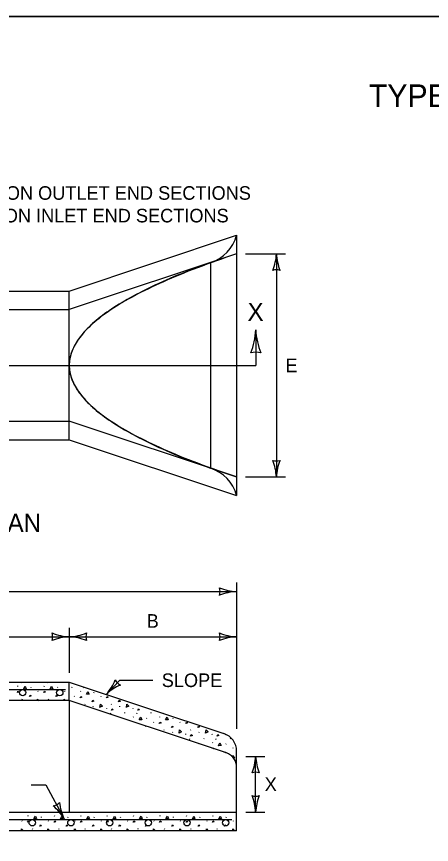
# Model space of a CAD drawing. Extents: x 49991.4 to 50021, y 49987.6 to 50011.4.
# Drawn here: x 50010.636 to 50012.469, y 49995.339 to 49998.999 of the extents above; entities that cross this region are included whole.
import ezdxf

# ---------------------------------------------------------------- set-up
doc = ezdxf.new("R2010")
doc.units = 0
for name, color, linetype in [('Level 1', 7, 'Continuous'), ('Level 2', 7, 'Continuous'), ('Level 3', 7, 'Continuous'), ('Level 4', 7, 'Continuous'), ('Level 6', 7, 'Continuous')]:
    doc.layers.add(name, color=color, linetype=linetype)

msp = doc.modelspace()

# ---------------------------------------------------------------- linework, layer by layer
at = {"layer": 'Level 1'}
for p, q in [((50010.8686, 49997.7858), (50011.6083, 49998.0325)), ((50011.6083, 49998.0325), (50011.6083, 49996.8818)), ((50011.4932, 49997.9121), (50011.4932, 49997.0023)), ((50009.6084, 49997.7858), (50010.8686, 49997.7858)), ((50010.8686, 49997.1282), (50010.8686, 49997.7858)), ((50009.6084, 49997.1282), (50010.8686, 49997.1282)), ((50010.8686, 49997.1282), (50011.6083, 49996.8818)), ((50009.6084, 49996.0573), (50010.8686, 49996.0573)), ((50010.6408, 49996.038), (50010.6418, 49996.0402)), ((50010.6552, 49996.0561), (50010.6562, 49996.0546)), ((50010.6562, 49996.0555), (50010.6572, 49996.0541)), ((50010.7195, 49996.0561), (50010.72, 49996.0573)), ((50010.7575, 49996.038), (50010.7585, 49996.0402)), ((50010.7719, 49996.0561), (50010.7729, 49996.0546)), ((50010.7729, 49996.0555), (50010.7738, 49996.0541)), ((50010.8362, 49996.0561), (50010.8367, 49996.0573)), ((50010.8686, 49996.0573), (50011.5522, 49995.8295)), ((50010.8686, 49995.975), (50010.8686, 49996.0573)), ((50010.8803, 49996.0334), (50010.8813, 49996.0356)), ((50010.6998, 49996.0324), (50010.7008, 49996.0346)), ((50010.7302, 49996.0169), (50010.7312, 49996.0154)), ((50010.8165, 49996.0324), (50010.8174, 49996.0346)), ((50010.8469, 49996.0169), (50010.8479, 49996.0154)), ((50010.9183, 49996.0153), (50010.9193, 49996.0175)), ((50010.9327, 49996.0334), (50010.9336, 49996.0319)), ((50010.9336, 49996.0328), (50010.9346, 49996.0314)), ((50010.9772, 49996.0097), (50010.9782, 49996.0119)), ((50010.8686, 49995.975), (50009.6906, 49995.975)), ((50010.6603, 49995.9806), (50010.6613, 49995.9827)), ((50010.777, 49995.9806), (50010.778, 49995.9827)), ((50011.5634, 49995.7435), (50010.8686, 49995.975)), ((50010.8686, 49995.975), (50010.8686, 49995.4819)), ((50010.891, 49995.9941), (50010.892, 49995.9927)), ((50011.0077, 49995.9941), (50011.0087, 49995.9927)), ((50010.9378, 49995.9578), (50010.9387, 49995.96)), ((50010.9748, 49995.9479), (50010.9758, 49995.95)), ((50011.0327, 49995.9417), (50011.033, 49995.9395)), ((50011.0545, 49995.9578), (50011.0554, 49995.96)), ((50011.0915, 49995.9479), (50011.0925, 49995.95)), ((50011.1494, 49995.9417), (50011.1497, 49995.9395)), ((50011.0493, 49995.9196), (50011.0503, 49995.9181)), ((50011.0503, 49995.919), (50011.0513, 49995.9176)), ((50011.1137, 49995.9196), (50011.1146, 49995.9218)), ((50011.1517, 49995.9015), (50011.1526, 49995.9037)), ((50011.166, 49995.9196), (50011.167, 49995.9181)), ((50011.167, 49995.919), (50011.168, 49995.9176)), ((50011.2106, 49995.8959), (50011.2116, 49995.8981)), ((50011.2303, 49995.9196), (50011.2313, 49995.9218)), ((50011.2684, 49995.9015), (50011.2693, 49995.9037)), ((50011.283, 49995.9192), (50011.2837, 49995.9181)), ((50011.2837, 49995.919), (50011.2847, 49995.9176)), ((50011.3273, 49995.8959), (50011.3283, 49995.8981)), ((50011.2411, 49995.8804), (50011.242, 49995.8789)), ((50011.3578, 49995.8804), (50011.3587, 49995.8789)), ((50011.2878, 49995.8441), (50011.2888, 49995.8462)), ((50011.3249, 49995.8341), (50011.3258, 49995.8363)), ((50011.3828, 49995.8279), (50011.383, 49995.8258)), ((50011.4045, 49995.8441), (50011.4055, 49995.8462)), ((50011.4416, 49995.8341), (50011.4425, 49995.8363)), ((50011.4995, 49995.8279), (50011.4997, 49995.8258)), ((50011.5584, 49995.8241), (50011.5591, 49995.8257)), ((50011.3994, 49995.8058), (50011.4004, 49995.8043)), ((50011.4004, 49995.8053), (50011.4014, 49995.8038)), ((50011.4445, 49995.7831), (50011.445, 49995.7843)), ((50011.4637, 49995.8058), (50011.4647, 49995.808)), ((50011.5017, 49995.7878), (50011.5027, 49995.7899)), ((50011.5161, 49995.8058), (50011.5171, 49995.8043)), ((50011.5171, 49995.8053), (50011.5181, 49995.8038)), ((50011.5607, 49995.7821), (50011.5617, 49995.7843)), ((50011.5804, 49995.8058), (50011.5814, 49995.808)), ((50011.5911, 49995.7666), (50011.5921, 49995.7651)), ((50011.6084, 49995.3998), (50011.6084, 49995.7515)), ((50009.6906, 49995.4819), (50011.6084, 49995.4819)), ((50010.6864, 49995.4645), (50010.6874, 49995.4667)), ((50010.7013, 49995.4819), (50010.7018, 49995.4811)), ((50010.7018, 49995.482), (50010.7028, 49995.4806)), ((50010.7454, 49995.4589), (50010.7464, 49995.4611)), ((50010.8031, 49995.4645), (50010.8041, 49995.4667)), ((50010.818, 49995.4819), (50010.8185, 49995.4811)), ((50010.8185, 49995.482), (50010.8195, 49995.4806)), ((50010.8621, 49995.4589), (50010.8631, 49995.4611)), ((50010.9198, 49995.4645), (50010.9208, 49995.4667)), ((50010.9347, 49995.4819), (50010.9352, 49995.4811)), ((50010.9352, 49995.482), (50010.9361, 49995.4806)), ((50010.9788, 49995.4589), (50010.9798, 49995.4611)), ((50011.0365, 49995.4645), (50011.0375, 49995.4667)), ((50011.0514, 49995.4819), (50011.0519, 49995.4811)), ((50011.0519, 49995.482), (50011.0528, 49995.4806)), ((50011.0955, 49995.4589), (50011.0964, 49995.4611)), ((50011.1532, 49995.4645), (50011.1542, 49995.4667)), ((50011.168, 49995.4819), (50011.1685, 49995.4811)), ((50011.1685, 49995.482), (50011.1695, 49995.4806)), ((50011.2122, 49995.4589), (50011.2131, 49995.4611)), ((50011.2699, 49995.4645), (50011.2709, 49995.4667)), ((50011.2847, 49995.4819), (50011.2852, 49995.4811)), ((50011.2852, 49995.482), (50011.2862, 49995.4806)), ((50011.3288, 49995.4589), (50011.3298, 49995.4611)), ((50011.3866, 49995.4645), (50011.3876, 49995.4667)), ((50011.4014, 49995.4819), (50011.4019, 49995.4811)), ((50011.4019, 49995.482), (50011.4029, 49995.4806)), ((50011.4455, 49995.4589), (50011.4465, 49995.4611)), ((50011.5033, 49995.4645), (50011.5042, 49995.4667)), ((50011.5181, 49995.4819), (50011.5186, 49995.4811)), ((50011.5186, 49995.482), (50011.5196, 49995.4806)), ((50011.5622, 49995.4589), (50011.5632, 49995.4611)), ((50010.6592, 49995.4434), (50010.6601, 49995.4419)), ((50010.7758, 49995.4434), (50010.7768, 49995.4419)), ((50010.8925, 49995.4434), (50010.8935, 49995.4419)), ((50011.0092, 49995.4434), (50011.0102, 49995.4419)), ((50011.1259, 49995.4434), (50011.1269, 49995.4419)), ((50011.2426, 49995.4434), (50011.2436, 49995.4419)), ((50011.3593, 49995.4434), (50011.3603, 49995.4419)), ((50011.476, 49995.4434), (50011.477, 49995.4419)), ((50011.5927, 49995.4434), (50011.5936, 49995.4419)), ((50011.6084, 49995.3998), (50009.6084, 49995.3998)), ((50010.7059, 49995.4071), (50010.7069, 49995.4092)), ((50010.8226, 49995.4071), (50010.8236, 49995.4092)), ((50010.9393, 49995.4071), (50010.9403, 49995.4092)), ((50011.056, 49995.4071), (50011.057, 49995.4092)), ((50011.1727, 49995.4071), (50011.1737, 49995.4092)), ((50011.2894, 49995.4071), (50011.2904, 49995.4092)), ((50011.4061, 49995.4071), (50011.407, 49995.4092)), ((50011.5228, 49995.4071), (50011.5237, 49995.4092))]:
    msp.add_line(p, q, dxfattribs=at)
msp.add_lwpolyline([(49999.3835, 49998.9992), (50016.7501, 49998.9992), (50016.7501, 49987.7988), (49999.3835, 49987.7988)], close=True, dxfattribs=at)
for points in [[(50010.6669, 49996.0259), (50010.6735, 49996.0383), (50010.6786, 49996.0268), (50010.6671, 49996.0259)], [(50010.7836, 49996.0259), (50010.7902, 49996.0383), (50010.7953, 49996.0268), (50010.7838, 49996.0259)], [(50009.7037, 49996.0243), (50010.8526, 49996.0243)], [(50010.6391, 49996.0105), (50010.642, 49996.0166), (50010.6469, 49996.013), (50010.6391, 49996.0105)], [(50010.6925, 49995.9931), (50010.6954, 49995.9992), (50010.7003, 49995.9955), (50010.6925, 49995.9931)], [(50010.7558, 49996.0105), (50010.7587, 49996.0166), (50010.7636, 49996.013), (50010.7558, 49996.0105)], [(50010.8092, 49995.9931), (50010.8121, 49995.9992), (50010.817, 49995.9955), (50010.8092, 49995.9931)], [(50010.9444, 49996.0032), (50010.9509, 49996.0156), (50010.956, 49996.0041), (50010.9446, 49996.0032)], [(50010.728, 49995.975), (50010.7289, 49995.982), (50010.7357, 49995.975)], [(50010.8447, 49995.975), (50010.8456, 49995.982), (50010.8524, 49995.975)], [(50010.9166, 49995.9878), (50010.9195, 49995.9939), (50010.9244, 49995.9902), (50010.9166, 49995.9878)], [(50010.97, 49995.9704), (50010.9729, 49995.9765), (50010.9778, 49995.9728), (50010.97, 49995.9704)], [(50011.0333, 49995.9878), (50011.0362, 49995.9939), (50011.0411, 49995.9902), (50011.0333, 49995.9878)], [(50011.0867, 49995.9704), (50011.0896, 49995.9765), (50011.0945, 49995.9728), (50011.0867, 49995.9704)], [(50011.0044, 49995.9453), (50011.0064, 49995.9593), (50011.0151, 49995.9503), (50011.0047, 49995.9454)], [(50011.055, 49995.9323), (50011.0579, 49995.9384), (50011.0627, 49995.9347), (50011.055, 49995.9323)], [(50011.1211, 49995.9453), (50011.1231, 49995.9593), (50011.1318, 49995.9503), (50011.1214, 49995.9454)], [(50011.1716, 49995.9323), (50011.1746, 49995.9384), (50011.1794, 49995.9347), (50011.1716, 49995.9323)], [(50011.1777, 49995.8894), (50011.1843, 49995.9018), (50011.1894, 49995.8903), (50011.178, 49995.8894)], [(50011.2944, 49995.8894), (50011.301, 49995.9018), (50011.3061, 49995.8903), (50011.2947, 49995.8894)], [(50011.2062, 49995.8625), (50011.2063, 49995.8627), (50011.2068, 49995.8623)], [(50011.2666, 49995.874), (50011.2696, 49995.8801), (50011.2744, 49995.8765), (50011.2666, 49995.874)], [(50011.32, 49995.8566), (50011.323, 49995.8627), (50011.3278, 49995.859), (50011.32, 49995.8566)], [(50011.3833, 49995.874), (50011.3863, 49995.8801), (50011.3911, 49995.8765), (50011.3833, 49995.874)], [(50011.4367, 49995.8566), (50011.4397, 49995.8627), (50011.4445, 49995.859), (50011.4367, 49995.8566)], [(50011.3545, 49995.8315), (50011.3564, 49995.8455), (50011.3652, 49995.8365), (50011.3547, 49995.8316)], [(50011.405, 49995.8185), (50011.4079, 49995.8246), (50011.4128, 49995.8209), (50011.405, 49995.8185)], [(50011.4712, 49995.8315), (50011.4731, 49995.8455), (50011.4819, 49995.8365), (50011.4714, 49995.8316)], [(50011.5217, 49995.8185), (50011.5246, 49995.8246), (50011.5295, 49995.8209), (50011.5217, 49995.8185)], [(50011.5278, 49995.7756), (50011.5344, 49995.788), (50011.5395, 49995.7765), (50011.528, 49995.7756)], [(50011.5018, 49995.764), (50011.5029, 49995.7663), (50011.5078, 49995.7627), (50011.5068, 49995.7624)], [(50011.5551, 49995.7463), (50011.5563, 49995.7489), (50011.5612, 49995.7452), (50011.5597, 49995.7447)], [(50011.5892, 49995.7271), (50011.5898, 49995.7317), (50011.5985, 49995.7227), (50011.594, 49995.7206)], [(50010.7125, 49995.4524), (50010.7191, 49995.4648), (50010.7242, 49995.4533), (50010.7128, 49995.4524)], [(50010.8292, 49995.4524), (50010.8358, 49995.4648), (50010.8409, 49995.4533), (50010.8294, 49995.4524)], [(50010.9459, 49995.4524), (50010.9525, 49995.4648), (50010.9576, 49995.4533), (50010.9461, 49995.4524)], [(50011.0626, 49995.4524), (50011.0692, 49995.4648), (50011.0743, 49995.4533), (50011.0628, 49995.4524)], [(50011.1793, 49995.4524), (50011.1858, 49995.4648), (50011.191, 49995.4533), (50011.1795, 49995.4524)], [(50011.296, 49995.4524), (50011.3025, 49995.4648), (50011.3077, 49995.4533), (50011.2962, 49995.4524)], [(50011.4126, 49995.4524), (50011.4192, 49995.4648), (50011.4243, 49995.4533), (50011.4129, 49995.4524)], [(50011.5293, 49995.4524), (50011.5359, 49995.4648), (50011.541, 49995.4533), (50011.5296, 49995.4524)], [(50009.706, 49995.4491), (50011.5866, 49995.4491)], [(50010.6847, 49995.437), (50010.6877, 49995.4431), (50010.6925, 49995.4395), (50010.6847, 49995.437)], [(50010.7381, 49995.4196), (50010.7411, 49995.4257), (50010.7459, 49995.422), (50010.7381, 49995.4196)], [(50010.8014, 49995.437), (50010.8043, 49995.4431), (50010.8092, 49995.4395), (50010.8014, 49995.437)], [(50010.8548, 49995.4196), (50010.8577, 49995.4257), (50010.8626, 49995.422), (50010.8548, 49995.4196)], [(50010.9181, 49995.437), (50010.921, 49995.4431), (50010.9259, 49995.4395), (50010.9181, 49995.437)], [(50010.9715, 49995.4196), (50010.9744, 49995.4257), (50010.9793, 49995.422), (50010.9715, 49995.4196)], [(50011.0348, 49995.437), (50011.0377, 49995.4431), (50011.0426, 49995.4395), (50011.0348, 49995.437)], [(50011.0882, 49995.4196), (50011.0911, 49995.4257), (50011.096, 49995.422), (50011.0882, 49995.4196)], [(50011.1515, 49995.437), (50011.1544, 49995.4431), (50011.1593, 49995.4395), (50011.1515, 49995.437)], [(50011.2049, 49995.4196), (50011.2078, 49995.4257), (50011.2127, 49995.422), (50011.2049, 49995.4196)], [(50011.2682, 49995.437), (50011.2711, 49995.4431), (50011.276, 49995.4395), (50011.2682, 49995.437)], [(50011.3216, 49995.4196), (50011.3245, 49995.4257), (50011.3294, 49995.422), (50011.3216, 49995.4196)], [(50011.3849, 49995.437), (50011.3878, 49995.4431), (50011.3927, 49995.4395), (50011.3849, 49995.437)], [(50011.4383, 49995.4196), (50011.4412, 49995.4257), (50011.4461, 49995.422), (50011.4383, 49995.4196)], [(50011.5016, 49995.437), (50011.5045, 49995.4431), (50011.5094, 49995.4395), (50011.5016, 49995.437)], [(50011.555, 49995.4196), (50011.5579, 49995.4257), (50011.5628, 49995.422), (50011.555, 49995.4196)], [(50010.6566, 49995.3998), (50010.6578, 49995.4085), (50010.6663, 49995.3998)], [(50010.7733, 49995.3998), (50010.7745, 49995.4085), (50010.783, 49995.3998)], [(50010.89, 49995.3998), (50010.8912, 49995.4085), (50010.8996, 49995.3998)], [(50011.0067, 49995.3998), (50011.0079, 49995.4085), (50011.0163, 49995.3998)], [(50011.1234, 49995.3998), (50011.1246, 49995.4085), (50011.133, 49995.3998)], [(50011.2401, 49995.3998), (50011.2413, 49995.4085), (50011.2497, 49995.3998)], [(50011.3568, 49995.3998), (50011.358, 49995.4085), (50011.3664, 49995.3998)], [(50011.4735, 49995.3998), (50011.4747, 49995.4085), (50011.4831, 49995.3998)], [(50011.5902, 49995.3998), (50011.5914, 49995.4085), (50011.5998, 49995.3998)]]:
    msp.add_lwpolyline(points, dxfattribs=at)
for centre in [(50010.6627, 49996.0104), (50010.8268, 49996.0104), (50010.705, 49995.4351), (50010.8759, 49995.4351), (50011.0469, 49995.4351), (50011.2179, 49995.4351), (50011.3888, 49995.4351), (50011.5598, 49995.4351)]:
    msp.add_circle(centre, 0.014, dxfattribs=at)
for centre, radius, start, end in [((50011.4431, 49998.0752), 0.1706, 287.0832, 345.4927), ((50011.4431, 49996.8391), 0.1706, 14.5073, 72.9168), ((50011.5261, 49995.7515), 0.0822, 0, 71.5597), ((50011.5426, 49995.6811), 0.0658, 0, 71.5569)]:
    msp.add_arc(centre, radius, start, end, dxfattribs=at)
for points in [[(50011.6083, 49997.9502), (50010.1288, 49997.457), (50011.6083, 49996.964)], [(50011.4932, 49997.9121), (50010.2439, 49997.457), (50011.4932, 49997.0023)]]:
    msp.add_open_spline(points, degree=2, dxfattribs=at)
at = {"layer": 'Level 2'}
msp.add_line((50016.7501, 49998.9992), (49999.3835, 49998.9992), dxfattribs=at)
at = {"layer": 'Level 3'}
for p, q in [((50011.6483, 49997.9502), (50011.8241, 49997.9502)), ((50011.7841, 49997.9502), (50011.7841, 49996.964)), ((50011.6483, 49996.964), (50011.8241, 49996.964)), ((50011.6084, 49996.4973), (50011.6084, 49995.9869)), ((50009.6084, 49996.4573), (50011.6084, 49996.4573)), ((50010.8686, 49996.2973), (50010.8686, 49996.0973)), ((50009.6084, 49996.2573), (50010.8686, 49996.2573)), ((50010.8686, 49996.2573), (50011.6084, 49996.2573)), ((50011.0927, 49996.0651), (50011.0324, 49996.0027)), ((50011.0927, 49996.0651), (50011.2374, 49996.0651)), ((50011.6084, 49995.9869), (50011.6084, 49995.8507)), ((50011.6484, 49995.7286), (50011.7325, 49995.7286)), ((50011.6925, 49995.4819), (50011.6925, 49995.7286)), ((50010.7, 49995.6034), (50010.7655, 49995.6034)), ((50010.7655, 49995.6034), (50010.846, 49995.4526)), ((50011.6484, 49995.4819), (50011.7325, 49995.4819))]:
    msp.add_line(p, q, dxfattribs=at)
for centre, radius, start, end in [((50011.5709, 49997.959), 0.2134, 337.456, 357.6395), ((50012.0075, 49997.9612), 0.2237, 182.8273, 202.0772), ((50011.7841, 49997.8271), 0.0526, 72.1388, 107.8612), ((50011.3969, 49997.6258), 0.2964, 337.456, 357.6395), ((50012.0034, 49997.6289), 0.3107, 182.8273, 202.0772), ((50011.6931, 49997.4426), 0.073, 72.1388, 107.8612), ((50011.7841, 49997.0871), 0.0526, 252.1388, 287.8612), ((50011.5607, 49996.953), 0.2237, 2.8273, 22.0772), ((50011.9973, 49996.9552), 0.2134, 157.456, 177.6395), ((50011.6176, 49996.6794), 0.2223, 247.456, 267.6395), ((50011.4802, 49996.4573), 0.0548, 342.1388, 17.8612), ((50011.6199, 49996.2246), 0.233, 92.8273, 112.0772), ((50010.8778, 49996.4794), 0.2223, 247.456, 267.6395), ((50010.7404, 49996.2573), 0.0548, 342.1388, 17.8612), ((50010.8801, 49996.0246), 0.233, 92.8273, 112.0772), ((50010.8571, 49996.49), 0.233, 272.8273, 292.0772), ((50010.8594, 49996.0352), 0.2223, 67.456, 87.6395), ((50010.9968, 49996.2573), 0.0548, 162.1388, 197.8612), ((50011.6176, 49996.4794), 0.2223, 247.456, 267.6395), ((50011.4802, 49996.2573), 0.0548, 342.1388, 17.8612), ((50011.6199, 49996.0246), 0.233, 92.8273, 112.0772), ((50010.8642, 49996.1501), 0.2237, 318.7754, 338.0252), ((50011.1796, 49995.8481), 0.2134, 113.4041, 133.5876), ((50011.118, 49996.0912), 0.0526, 208.0869, 243.8093), ((50011.4793, 49995.7374), 0.2134, 337.456, 357.6395), ((50011.9159, 49995.7396), 0.2237, 182.8273, 202.0772), ((50011.6925, 49995.6055), 0.0526, 72.1388, 107.8612), ((50010.7881, 49995.5612), 0.0526, 280.2056, 315.928), ((50011.0383, 49995.5452), 0.2134, 185.5228, 205.7063), ((50011.6925, 49995.605), 0.0526, 252.1388, 287.8612), ((50011.4691, 49995.4709), 0.2237, 2.8273, 22.0772), ((50011.9057, 49995.4731), 0.2134, 157.456, 177.6395), ((50010.6541, 49995.3378), 0.2237, 30.8941, 50.144)]:
    msp.add_arc(centre, radius, start, end, dxfattribs=at)
at = {"layer": 'Level 4'}
for p, q in [((50011.6083, 49997.9502), (50010.8686, 49997.7037)), ((50009.6906, 49997.7037), (50010.8686, 49997.7037)), ((50009.6906, 49997.2105), (50010.8686, 49997.2105)), ((50011.6083, 49996.964), (50010.8686, 49997.2105))]:
    msp.add_line(p, q, dxfattribs=at)
at = {"layer": 'Level 6'}
for p in [(50011.6931, 49997.6136), (50009.528, 49997.457)]:
    msp.add_line(p, (50011.6931, 49997.457), dxfattribs=at)

# ---------------------------------------------------------------- texts
at = {"layer": 'Level 2'}
for s, height, p in [('TYPE "B"', 0.1, (50012.1927, 49998.5992)), ('GROOVE END ON OUTLET END SECTIONS', 0.06, (50010.022, 49998.1892)), ('TONGUE END ON INLET END SECTIONS', 0.06, (50010.022, 49998.0892)), ('X', 0.08, (50011.6564, 49997.6536)), ('E', 0.06, (50011.8241, 49997.4271)), ('PLAN', 0.08, (50010.4646, 49996.721)), ('B', 0.06, (50011.2108, 49996.2973)), ('SLOPE', 0.06, (50011.2774, 49996.0351)), ('X', 0.06, (50011.7325, 49995.5753))]:
    msp.add_text(s, height=height, dxfattribs=at).set_placement(p)

doc.saveas('drawing.dxf')
